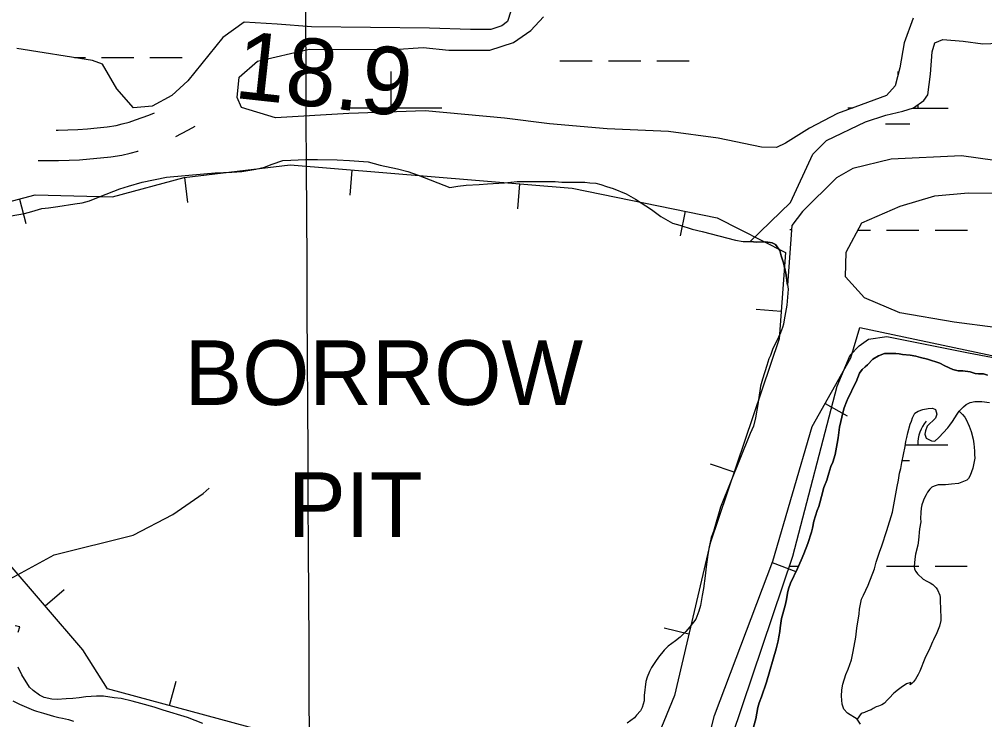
# Model space of a CAD drawing. Extents: x 3445503 to 3483459, y 540493 to 566012.
# Drawn here: x 3465171 to 3466127, y 549488 to 550181 of the extents above; entities that cross this region are included whole.
import ezdxf

# ---------------------------------------------------------------- set-up
doc = ezdxf.new("R2010")
doc.units = 0
for name, color, linetype in [('V-BORW-IDEN', 7, 'Continuous'), ('V-BORW-LINE', 7, 'Continuous'), ('V-GRID-MAJR', 7, 'Continuous'), ('V-RIVR-RANG', 7, 'Continuous'), ('V-ROAD-CNTR', 7, 'Continuous'), ('V-SITE-VEGE', 7, 'Continuous'), ('V-WETL-SWMP', 7, 'Continuous')]:
    doc.layers.add(name, color=color, linetype=linetype)

msp = doc.modelspace()

# ---------------------------------------------------------------- linework, layer by layer
at = {"layer": 'V-BORW-LINE'}
for p, q in [((3465500.25, 550032.11), (3465498.2, 550007.2)), ((3465334.57, 550024.89), (3465337.48, 550000.06)), ((3465666.29, 550018.45), (3465664.24, 549993.54)), ((3465171.1, 550003.39), (3465177.44, 549979.21)), ((3465830.41, 549991.34), (3465825.41, 549966.85)), ((3465925.41, 549892.08), (3465900.47, 549893.86)), ((3465968.92, 549800.88), (3465990.71, 549788.62)), ((3465878.9, 549732.87), (3465855.21, 549740.86)), ((3465916.45, 549643.36), (3465939.83, 549634.52)), ((3465196.55, 549600.54), (3465215.54, 549616.8)), ((3465833.95, 549572.64), (3465809.61, 549578.38)), ((3465319.87, 549501.9), (3465326.41, 549526.03))]:
    msp.add_line(p, q, dxfattribs=at)
for points in [[(3465130.41, 549992.72), (3465186.77, 550007.5), (3465263.39, 550005.6), (3465334.25, 550024.86), (3465439.09, 550037.15), (3465718.55, 550014.16), (3465861.85, 549984.93), (3465929.57, 549950.46), (3465923.48, 549864.96), (3465855.14, 549662.48), (3465819.57, 549511.71), (3465766.32, 549381.24), (3465712.77, 549389.4), (3465451.24, 549466.3), (3465258.51, 549518.53), (3465233.93, 549556.88), (3465158.14, 549645.41), (3465122.03, 549784.78), (3465105.03, 549923.2), (3465130.41, 549992.72)], [(3466003.27, 549876.22), (3466392.29, 549793.52), (3466427.8, 549740.04), (3466432.65, 549676.39), (3466416.32, 549455.95), (3466389.68, 549315.79), (3466362.94, 549240.53), (3466321, 549217.1), (3466184.24, 549239.25), (3466035.78, 549280.82), (3465880.64, 549322.3), (3465829.87, 549375.12), (3465859.19, 549491.93), (3465916.93, 549644.64), (3465956.06, 549778.04), (3465994.35, 549846.05), (3466003.27, 549876.22)]]:
    msp.add_lwpolyline(points, dxfattribs=at)
at = {"layer": 'V-GRID-MAJR'}
msp.add_spline([(3465476.12, 545965.82), (3465445.29, 552023.32), (3465414.43, 558084.29), (3465383.58, 564145.27), (3465383.56, 564148.72)], degree=3, dxfattribs=at)
at = {"layer": 'V-ROAD-CNTR'}
for points in [[(3465207.49, 550071.53), (3465209.48, 550071.55), (3465219.19, 550071.81), (3465228.9, 550072.29), (3465238.59, 550072.98), (3465248.26, 550073.88), (3465257.92, 550074.99), (3465266.89, 550076.21), (3465273.02, 550077.75), (3465279.67, 550079.62), (3465286.26, 550081.7), (3465292.77, 550083.98), (3465299.21, 550086.45), (3465304.94, 550088.84)], [(3465325.97, 550065.48), (3465331.69, 550068.3), (3465338.58, 550071.95), (3465345.16, 550075.7)], [(3465189.79, 550041.64), (3465199.61, 550041.49), (3465209.98, 550041.55), (3465220.35, 550041.83), (3465230.7, 550042.34), (3465241.04, 550043.08), (3465251.36, 550044.04), (3465261.66, 550045.22), (3465272.58, 550046.71), (3465280.74, 550048.75), (3465288.26, 550050.88), (3465288.88, 550051.07)], [(3466363.82, 549172.42), (3465951.36, 549278.7), (3465716.31, 549337.55), (3465501.91, 549385.94), (3465377.9, 549418.5), (3465193.79, 549468.46), (3465105.19, 549493.59), (3465104.29, 549545.84), (3465136.14, 549613.53), (3465205.58, 549651.14), (3465283.84, 549670.49), (3465323.19, 549691.03), (3465353.24, 549711.69), (3465359.13, 549717.01)]]:
    msp.add_lwpolyline(points, dxfattribs=at)
at = {"layer": 'V-SITE-VEGE'}
for points in [[(3465163.08, 549986.79), (3465176.09, 549989.1), (3465183.36, 549990.93), (3465193.27, 549994.1), (3465199.89, 549994.81), (3465209.15, 549995.99), (3465226.14, 549998.55), (3465233.2, 549999.49), (3465240.69, 550001.76), (3465251.25, 550005.82), (3465270.62, 550013.48), (3465279.21, 550016.2), (3465292.65, 550020.06), (3465316.68, 550025.1), (3465353.76, 550028.49), (3465365.01, 550029.24), (3465381.34, 550030.03), (3465391.27, 550030.78), (3465405.39, 550033.1), (3465413.77, 550034.93), (3465421.25, 550037.86), (3465431.82, 550041.48), (3465439.99, 550041.98), (3465454.34, 550042.54), (3465466.26, 550042.63), (3465485.92, 550042.35), (3465498.07, 550041.56), (3465516.41, 550040.16), (3465528.36, 550036.94), (3465545.61, 550033.32), (3465555.79, 550030.76), (3465565.97, 550027.08), (3465597.21, 550014.96), (3465605.37, 550016.13), (3465613.53, 550017.08), (3465626.33, 550017.84), (3465634.72, 550018.57), (3465651.49, 550019.59), (3465663.85, 550020.79), (3465671.58, 550020.85), (3465683.06, 550020.72), (3465690.57, 550020.78), (3465701.61, 550020.65), (3465708.02, 550020.26), (3465717.73, 550020.11), (3465730.98, 550020.22), (3465735.84, 550019.59), (3465741.81, 550018.98), (3465746.9, 550017.92), (3465752.43, 550015.97), (3465759.07, 550013.82), (3465771.71, 550008.4), (3465781.24, 550003.17), (3465797, 549992.92), (3465806.11, 549986.15), (3465817.64, 549979.61), (3465824.95, 549977.46), (3465837.12, 549973.58), (3465847.08, 549971.24), (3465880.27, 549962.67), (3465887.79, 549961.4), (3465894.64, 549961.23), (3465901.26, 549960.84), (3465910.09, 549960.92), (3465916.28, 549960.08), (3465919.61, 549958.34), (3465923.85, 549952.41), (3465925.44, 549947.12), (3465927.7, 549940.3), (3465929.99, 549929.94), (3465932.33, 549914.06), (3465930.91, 549898.37), (3465928.37, 549883.77), (3465927.74, 549879.57), (3465926.67, 549876.25), (3465924.5, 549870.93), (3465922.55, 549866.5), (3465916.68, 549854.53), (3465914.74, 549848.55), (3465913, 549845.23), (3465911.06, 549838.59), (3465906.75, 549825.08), (3465904.82, 549818)], [(3466008.36, 549837.19), (3466010.67, 549839.37), (3466016.02, 549844.76), (3466021.66, 549848.11), (3466027.6, 549850.3), (3466038.76, 549850.33), (3466042.24, 549850.2), (3466045.43, 549849.48), (3466053.11, 549848.92), (3466058.77, 549847.78), (3466063.27, 549846.34), (3466070.23, 549844.91), (3466082.42, 549840.89), (3466087.36, 549838.15), (3466095.34, 549834.55), (3466100.71, 549833.41), (3466105.06, 549833.13), (3466112.45, 549832.14), (3466117.39, 549830.7), (3466120.72, 549830.28), (3466125.65, 549830.15), (3466129.71, 549828.85)], [(3465898.07, 549480.27), (3465900.08, 549488.69), (3465902.22, 549499.85), (3465903.65, 549504.49), (3465905.81, 549510.44), (3465910.84, 549525.1), (3465920.46, 549558.03), (3465922.32, 549566.01), (3465923.03, 549569.93), (3465923.89, 549575.15), (3465924.31, 549578.78), (3465925.73, 549587.91), (3465929.17, 549600.97), (3465930.61, 549606.92), (3465931.6, 549613.01), (3465932.61, 549617.36), (3465934.62, 549623.16), (3465941.53, 549637.68), (3465945.13, 549645.66), (3465947.87, 549652.05), (3465951.75, 549662.35), (3465955.35, 549673.52), (3465956.35, 549677.44), (3465957.78, 549684.26), (3465961.08, 549694.99), (3465962.52, 549699.06), (3465963.52, 549702.54), (3465965.1, 549708.92), (3465967.68, 549717.63), (3465970.41, 549724.89), (3465972.42, 549731.99), (3465974.58, 549738.38), (3465976.45, 549742.88), (3465978.75, 549750.57), (3465980.89, 549761.45), (3465981.74, 549766.96), (3465983.16, 549777.54), (3465986.74, 549793.06), (3465987.75, 549796.69), (3465989.9, 549802.64), (3465991.63, 549806.56), (3465994.37, 549811.64), (3465996.1, 549815.42), (3465999.56, 549822.38), (3466003.01, 549830.95), (3466005.46, 549834.72), (3466008.36, 549837.19)], [(3465904.82, 549818), (3465902.72, 549804.51), (3465902.32, 549800.1), (3465899.77, 549786.61), (3465898.07, 549778.64), (3465894.6, 549771.11), (3465865.14, 549698.22), (3465860.42, 549681.18), (3465858.27, 549674.1), (3465856.11, 549668.12), (3465853.97, 549658.83), (3465852.71, 549651.53), (3465851.04, 549639.15), (3465850, 549630.31), (3465848.34, 549617.71), (3465847.07, 549610.86), (3465845.38, 549600.91), (3465843.88, 549595.38), (3465840.85, 549587.4), (3465834.95, 549579.62), (3465830.79, 549575.18), (3465825.31, 549569.61), (3465820.7, 549566.04), (3465813.46, 549560.69), (3465809.51, 549556.68), (3465803.83, 549549.57), (3465800.77, 549545.57), (3465796.85, 549539.35), (3465794.89, 549535.58), (3465792.5, 549529.82), (3465791.21, 549525.62), (3465789.77, 549511.7), (3465789.6, 549506.4), (3465787.66, 549499.97), (3465785.92, 549496.65), (3465782.2, 549492.42), (3465780.01, 549489.76), (3465772.99, 549484.4)], [(3466101.69, 549793.4), (3466104.89, 549790.08), (3466107.22, 549787.33), (3466108.53, 549785.01), (3466111.31, 549778.64), (3466113.35, 549773.28), (3466115.55, 549765.61), (3466116.14, 549760.83), (3466116.29, 549757.78), (3466116.74, 549753.73), (3466116.75, 549750.54), (3466116.9, 549746.91), (3466116.2, 549741.98), (3466115.19, 549737.05), (3466112.46, 549729.5), (3466110.73, 549726.6), (3466109.29, 549725.15), (3466100.89, 549721.79), (3466094.08, 549721.04), (3466091.03, 549720.6), (3466088.14, 549720.45), (3466080.74, 549720.42), (3466076.69, 549718.96), (3466074.37, 549717.94), (3466072.35, 549716.19), (3466070.18, 549713.14), (3466068.74, 549710.53), (3466066.72, 549706.32), (3466065.86, 549704.29), (3466064.56, 549700.66), (3466063.85, 549697.33), (3466063.43, 549692.83), (3466063.3, 549686.89), (3466063.46, 549683.84), (3466062.32, 549676.88), (3466061.33, 549665.57), (3466060.77, 549660.79), (3466058.47, 549651.79), (3466057.62, 549646.72), (3466057.06, 549639.47), (3466057.36, 549636.86), (3466058.53, 549634.4), (3466060.13, 549632.37), (3466065.94, 549627.03), (3466069.57, 549625.01), (3466072.91, 549623.42), (3466075.52, 549621.69), (3466078.87, 549618.51), (3466080.18, 549616.34), (3466082.37, 549611.27), (3466082.81, 549608.67), (3466083, 549594.32), (3466083.29, 549591.56), (3466083.31, 549586.05), (3466082.17, 549580.54), (3466079.43, 549573.72), (3466076.27, 549566.75), (3466075.26, 549564.87), (3466072.52, 549558.77), (3466067.48, 549548.32), (3466062.58, 549535.98), (3466061, 549532.5), (3466058.26, 549527.99), (3466056.38, 549525.24), (3466054.65, 549523.49), (3466052.91, 549522.18), (3466053.63, 549524.5), (3466049.43, 549523.19), (3466044.22, 549519.84), (3466041.33, 549517.8), (3466036.99, 549514.02), (3466032.08, 549509.22), (3466030.34, 549507.04), (3466027.6, 549504.28), (3466025.14, 549502.53), (3466021.66, 549501.36), (3466019.49, 549500.48), (3466016.3, 549498.88), (3466014.28, 549497.57), (3466011.38, 549496.55), (3466007.76, 549495.09), (3466004.43, 549493.92), (3466000.54, 549488.25), (3465991.1, 549494.31), (3465987.31, 549498.22), (3465985.85, 549503.14), (3465985.4, 549507.05), (3465985.1, 549510.97), (3465985.37, 549517.49), (3465986.37, 549522.86), (3465989.39, 549532.43), (3465991.69, 549537.8), (3465994.86, 549547.23), (3465996.57, 549555.36), (3465999.14, 549569.57), (3466000.27, 549578.56), (3466002.41, 549592.48), (3466002.97, 549597.41), (3466004.97, 549607.13), (3466006.7, 549611.2), (3466011.6, 549621.07)], [(3466011.6, 549621.07), (3466017.79, 549637.18), (3466019.5, 549643.85), (3466022.52, 549653.57), (3466024.82, 549660.1), (3466029.85, 549675.05), (3466035.45, 549693.19), (3466037.59, 549704.35), (3466038.02, 549707.83), (3466040.31, 549718.71), (3466041.45, 549724.95), (3466042.58, 549731.91), (3466043.73, 549736.41), (3466044.73, 549742.35), (3466048.16, 549758.31), (3466048.87, 549763.24), (3466049.88, 549767.16), (3466050.73, 549771.94), (3466053.17, 549780.5), (3466054.47, 549783.41), (3466055.47, 549786.89), (3466057.49, 549791.24), (3466060.96, 549793.43), (3466065.59, 549794.89), (3466070.95, 549795.92), (3466075.01, 549796.22), (3466078.21, 549794.93), (3466079.52, 549790.44), (3466078.23, 549786.37), (3466069.85, 549778.52), (3466068.12, 549774.02), (3466067.7, 549770.54), (3466069.01, 549766.63), (3466074.09, 549764.04), (3466077.43, 549763.76), (3466081.48, 549767.1), (3466090.29, 549776.7), (3466092.17, 549779.46), (3466095.05, 549783.09), (3466099.53, 549790.35), (3466101.69, 549793.4)], [(3465170.1, 549574.57), (3465171.6, 549579.66), (3465167.04, 549580.76)], [(3465352.77, 549484.16), (3465337.71, 549490.01), (3465313.36, 549497.1), (3465304.73, 549500.12), (3465291.22, 549503.99), (3465282.82, 549506.13), (3465271.98, 549508.69), (3465264.9, 549509.52), (3465254.51, 549511.21), (3465247.45, 549511.15), (3465237.07, 549510.41), (3465230.46, 549509.47), (3465224.06, 549508.76), (3465217.44, 549508.48), (3465208.61, 549507.75), (3465203.31, 549508.15), (3465195.56, 549509.63), (3465190.91, 549512.25), (3465184.91, 549516.62), (3465181.13, 549520.12), (3465173.53, 549532.2), (3465169.93, 549539.91)], [(3465164.79, 549506.53), (3465171.32, 549503.07), (3465185.11, 549497.31), (3465188.16, 549496.16), (3465195.12, 549494.3), (3465198.46, 549493.15), (3465204.99, 549491.29), (3465210.06, 549489.99), (3465213.83, 549489.28), (3465219.93, 549487.85), (3465224.86, 549486.42)]]:
    msp.add_lwpolyline(points, dxfattribs=at)
at = {"layer": 'V-WETL-SWMP'}
for p, q in [((3465225.57, 550143.59), (3465236.44, 550143.59)), ((3465252.44, 550143.59), (3465284.44, 550143.59)), ((3465300.44, 550143.59), (3465332.44, 550143.59)), ((3465706.32, 550140.17), (3465738.32, 550140.17)), ((3465754.32, 550140.17), (3465786.32, 550140.17)), ((3465802.32, 550140.17), (3465834.32, 550140.17)), ((3465539.26, 550093.74), (3465539.26, 550129.74)), ((3466041.16, 550126.62), (3466041.16, 550129.74)), ((3465489.27, 550093.74), (3465589.26, 550093.74)), ((3465991.17, 550093.74), (3465996.52, 550093.74)), ((3466055.09, 550093.31), (3466090.72, 550093.31)), ((3466028.72, 550077.88), (3466052.72, 550077.88)), ((3465933.88, 549973.25), (3465935.68, 549973.25)), ((3466001.3, 549972.62), (3466013.65, 549972.62)), ((3466029.65, 549972.62), (3466061.65, 549972.62)), ((3466077.65, 549972.62), (3466109.65, 549972.62)), ((3466048.4, 549759.99), (3466090.47, 549759.99)), ((3466045.2, 549744.56), (3466052.47, 549744.56)), ((3465933.63, 549639.92), (3465942.54, 549639.92)), ((3466029.63, 549639.92), (3466061.63, 549639.92)), ((3466077.63, 549639.92), (3466109.63, 549639.92))]:
    msp.add_line(p, q, dxfattribs=at)
for points in [[(3465657.79, 550189.59), (3465654.25, 550179.26), (3465648.71, 550174.88), (3465638.01, 550171.28), (3465617.77, 550171.22), (3465577.29, 550172.69), (3465460.21, 550173.93), (3465426.47, 550176.61), (3465393.53, 550178.5), (3465372.54, 550163.35), (3465337.75, 550120.39), (3465321.92, 550106.06), (3465302.5, 550095.29), (3465284.25, 550093.65), (3465267.53, 550112.65), (3465253.57, 550136.81), (3465243.64, 550140.75), (3465168.6, 550152.44)], [(3466055.9, 550182.64), (3466047.24, 550158.01), (3466042.95, 550133.4), (3466038.24, 550115.53), (3466029.54, 550105.97), (3466004.56, 550096.78), (3465981.18, 550087.98), (3465953.44, 550073.61), (3465929.67, 550058.85), (3465920.56, 550054.46), (3465905.87, 550054.82), (3465862.99, 550063.82), (3465813.76, 550070.42), (3465753.04, 550073.02), (3465695.88, 550078.01), (3465651.41, 550083.44), (3465572.82, 550090.75), (3465497.43, 550088.15), (3465424.81, 550083.96), (3465391.05, 550094.18), (3465386.66, 550104.09), (3465388.58, 550123.94), (3465406.79, 550139.87), (3465457.95, 550151.92), (3465541.69, 550151.37), (3465571.05, 550153.44), (3465596.45, 550150.74), (3465636.93, 550150.86), (3465660.32, 550158.47), (3465677.35, 550170.42), (3465690.01, 550183.95)], [(3466203.02, 550032.18), (3466103.92, 550046.22), (3466034.19, 550042.76), (3465996.42, 550033.52), (3465980.15, 550024.35), (3465946.36, 549991.02), (3465935.97, 549977.3), (3465931.73, 549918.09), (3465929.99, 549929.94), (3465927.7, 549940.3), (3465925.44, 549947.12), (3465923.85, 549952.41), (3465919.61, 549958.34), (3465916.28, 549960.08), (3465910.09, 549960.92), (3465901.26, 549960.84), (3465894.63, 549961.23), (3465934.6, 550000.1), (3465956.62, 550047.75), (3465970.27, 550061.47), (3466008.66, 550079.83), (3466028.85, 550086.41), (3466045.78, 550090.37), (3466056.2, 550093.66), (3466066.61, 550100.86), (3466070.5, 550106.73), (3466073.05, 550126.95), (3466074.94, 550149.11), (3466077.52, 550158.24), (3466085.33, 550161.52), (3466105.54, 550159.63), (3466125.1, 550157.08), (3466172.02, 550159.17)], [(3466137.31, 549876.11), (3466096.53, 549881.32), (3466042.68, 549890.78), (3466007.76, 549905.53), (3465989.01, 549926.34), (3465989.6, 549950.87), (3466005.19, 549979.86), (3466043.02, 549996.37), (3466077.35, 550006.53), (3466110.54, 550009.56), (3466152.07, 550009.1)], [(3466256.17, 549243.24), (3466089.15, 549279.26), (3465951.48, 549314.71), (3465916.24, 549325.04), (3465895.35, 549336.06), (3465877.72, 549345.14), (3465867.25, 549358.8), (3465862.65, 549369.87), (3465859.32, 549393.98), (3465867, 549442.25), (3465936.81, 549649.79), (3465980.65, 549818.13), (3465993.6, 549848.81), (3466002.7, 549857.96), (3466011.81, 549864.51), (3466030.06, 549867.17), (3466110.95, 549851.11), (3466388.85, 549798.46)], [(3466129.71, 549828.85), (3466125.65, 549830.15), (3466120.72, 549830.28), (3466117.39, 549830.7), (3466112.45, 549832.14), (3466105.06, 549833.13), (3466100.71, 549833.41), (3466095.34, 549834.55), (3466087.36, 549838.15), (3466082.42, 549840.89), (3466070.23, 549844.91), (3466063.27, 549846.34), (3466058.77, 549847.78), (3466053.11, 549848.92), (3466045.43, 549849.48), (3466042.24, 549850.2), (3466038.76, 549850.33), (3466027.6, 549850.3), (3466021.66, 549848.11), (3466016.02, 549844.76), (3466010.67, 549839.38), (3466008.36, 549837.2), (3466005.46, 549834.72), (3466003.01, 549830.95), (3465999.56, 549822.38), (3465996.1, 549815.42), (3465994.37, 549811.64), (3465991.63, 549806.56), (3465989.9, 549802.64), (3465987.75, 549796.69), (3465986.74, 549793.06), (3465983.16, 549777.54), (3465981.74, 549766.96), (3465980.89, 549761.45), (3465978.75, 549750.57), (3465976.45, 549742.88), (3465974.58, 549738.38), (3465972.42, 549731.99), (3465970.42, 549724.89), (3465967.68, 549717.63), (3465965.1, 549708.92), (3465963.52, 549702.54), (3465962.52, 549699.06)], [(3466050.73, 549771.94), (3466053.17, 549780.5), (3466054.47, 549783.41), (3466055.47, 549786.89), (3466057.49, 549791.24), (3466060.96, 549793.43), (3466065.59, 549794.89), (3466070.95, 549795.92), (3466075.01, 549796.22), (3466078.21, 549794.93), (3466079.52, 549790.44), (3466078.23, 549786.37), (3466069.85, 549778.52), (3466068.12, 549774.02), (3466067.7, 549770.54), (3466069.01, 549766.63), (3466074.09, 549764.04), (3466077.43, 549763.76), (3466081.48, 549767.1), (3466090.29, 549776.7), (3466092.17, 549779.46), (3466095.06, 549783.09), (3466099.53, 549790.35), (3466101.69, 549793.4), (3466105.74, 549797.62), (3466108.63, 549800.09), (3466112.4, 549801.98), (3466117.03, 549803.01), (3466123.84, 549803.03), (3466131.68, 549802.04)], [(3466003.88, 549483.33), (3466000.54, 549488.25), (3465991.1, 549494.31), (3465987.31, 549498.22), (3465985.85, 549503.14), (3465985.41, 549507.05), (3465985.1, 549510.97), (3465985.37, 549517.49), (3465986.37, 549522.86), (3465989.39, 549532.43), (3465991.69, 549537.8), (3465994.85, 549547.23), (3465996.57, 549555.36), (3465999.14, 549569.57), (3466000.27, 549578.56), (3466002.41, 549592.48), (3466002.97, 549597.42), (3466004.97, 549607.13), (3466006.7, 549611.2), (3466011.6, 549621.07), (3466017.79, 549637.18), (3466019.5, 549643.85), (3466022.52, 549653.57), (3466024.82, 549660.1), (3466029.85, 549675.05), (3466035.45, 549693.18), (3466037.59, 549704.35), (3466038.02, 549707.83), (3466040.3, 549718.71), (3466041.45, 549724.95), (3466042.58, 549731.91), (3466043.73, 549736.41), (3466044.73, 549742.35), (3466048.16, 549758.31), (3466048.87, 549763.24), (3466049.88, 549767.16), (3466050.73, 549771.94)], [(3465962.52, 549699.06), (3465961.08, 549694.99), (3465957.78, 549684.26), (3465956.35, 549677.44), (3465955.35, 549673.53), (3465951.75, 549662.35), (3465947.87, 549652.05), (3465945.14, 549645.66), (3465941.53, 549637.68), (3465934.62, 549623.16), (3465932.61, 549617.36), (3465931.6, 549613.01), (3465930.61, 549606.92), (3465929.18, 549600.97), (3465925.73, 549587.91), (3465924.31, 549578.78), (3465923.89, 549575.15), (3465923.03, 549569.93), (3465922.32, 549566.01), (3465920.46, 549558.03), (3465910.84, 549525.1), (3465905.81, 549510.45), (3465903.66, 549504.49), (3465902.22, 549499.85), (3465900.08, 549488.68), (3465898.07, 549480.27)]]:
    msp.add_lwpolyline(points, dxfattribs=at)
for centre, start, end in [((3466095.97, 550093.79), 174.96223, 180.77178), ((3466095.71, 549760.46), 139.22818, 180.77184)]:
    msp.add_arc(centre, 35.25, start, end, dxfattribs=at)

# ---------------------------------------------------------------- texts
at = {"layer": 'V-BORW-IDEN'}
for s, p in [('BORROW', (3465334.6, 549799.49)), ('PIT', (3465437.15, 549668.73))]:
    msp.add_text(s, height=64, dxfattribs=at).set_placement(p)
at = {"layer": 'V-RIVR-RANG'}
msp.add_text('18.9', height=67, rotation=353.73833, dxfattribs=at).set_placement((3465382.72, 550103.72))

doc.saveas('drawing.dxf')
